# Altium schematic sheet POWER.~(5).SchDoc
size 431 x 279 mm; Date: Not shown in title block; ApprovedBy: Not shown in title block; CheckedBy: Not shown in title block; Author: Not shown in title block; CompanyName: Not shown in title block; DrawnBy: G. Fiolic; Engineer: Not shown in title block; Organization: Not shown in title block; Address1: Not shown in title block; Address2: Not shown in title block; Address3: Not shown in title block; Address4: Not shown in title block; DocumentNumber: 3; Revision: Use project parameter SCH_Rev; SheetNumber: 3; SheetTotal: 6; PageSetup: Record=PageOptions|CenterHorizontal=True|CenterVertical=True|PrintScale=1.00|XCorrection=1.00|YCorrection=1.00|PrintKind=0|BorderSize=5000000|LeftOffset=0|BottomOffset=0|Orientation=2|PaperLength=1000|PaperWidth=1000|Scale=100|PaperSource=15|PrintQuality=600|MediaType=1|DitherType=10|PaperKind=Letter|PrintScaleMode=1
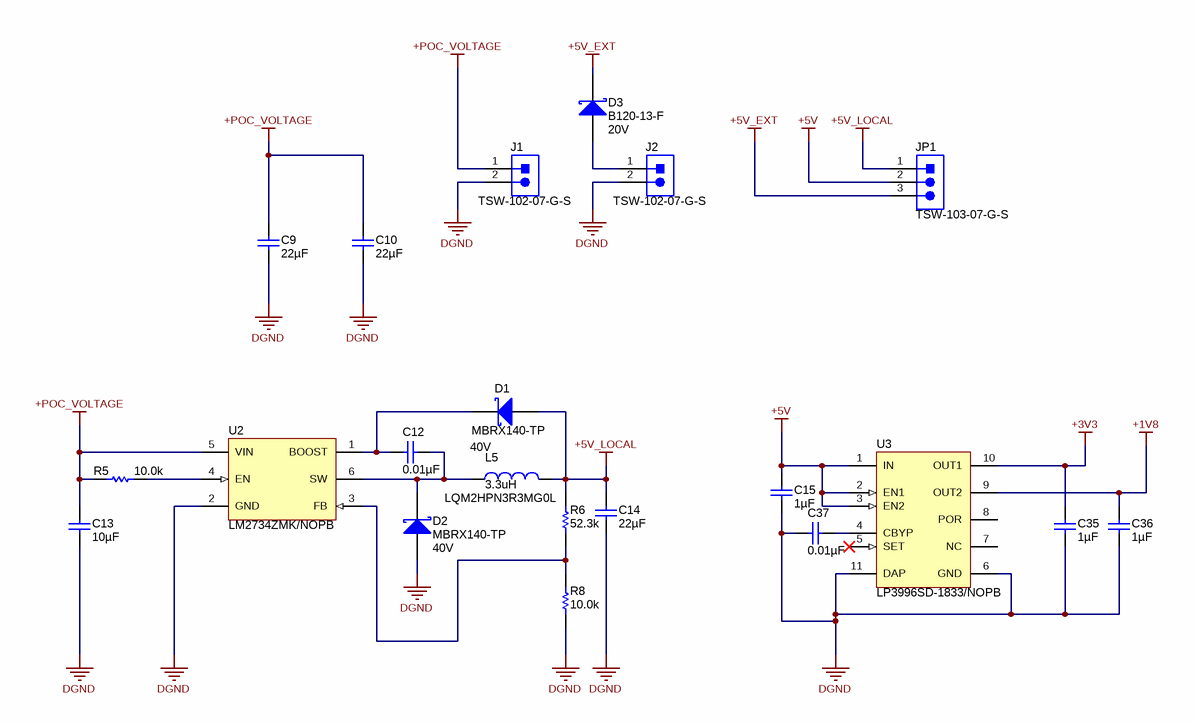
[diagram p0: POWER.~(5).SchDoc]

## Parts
C9  ValueDisplayed: 22µF  [0805]  (hidden comment: C2012X5R1C226K125AC)
C10  ValueDisplayed: 22µF  [0805]  (hidden comment: C2012X5R1C226K125AC)
C12  ValueDisplayed: 0.01µF  [0402L]  (hidden comment: GRM155R71H103KA88D)
C13  ValueDisplayed: 10µF  [1206L]  (hidden comment: GRM31CR71E106KA12L)
C14  ValueDisplayed: 22µF  [0805]  (hidden comment: C2012X5R1C226K125AC)
C15  ValueDisplayed: 1µF  [0402]  (hidden comment: GRM155R61A105KE15D)
C35  ValueDisplayed: 1µF  [0402]  (hidden comment: GRM155R61A105KE15D)
C36  ValueDisplayed: 1µF  [0402]  (hidden comment: GRM155R61A105KE15D)
C37  ValueDisplayed: 0.01µF  [0402L]  (hidden comment: GRM155R71H103KA88D)
D1  MBRX140-TP  value 40V  [SOD-123]
D2  MBRX140-TP  value 40V  [SOD-123]
D3  B120-13-F  value 20V  [SMA]
J1  TSW-102-07-G-S  [TSW-102-07-G-S]
J2  TSW-102-07-G-S  [TSW-102-07-G-S]
JP1  TSW-103-07-G-S  [TSW-103-07-G-S]
L5  LQM2HPN3R3MG0L  value 3.3uH  [IND_1008]
R5  value 10.0k  [0402L]  (hidden comment: CRCW040210K0FKED)
R6  value 52.3k  [0402]  (hidden comment: CRCW040252K3FKED)
R8  value 10.0k  [0402L]  (hidden comment: CRCW040210K0FKED)
U2  LM2734ZMK/NOPB  [MK06A_N]
U3  LP3996SD-1833/NOPB  [SDA10A]

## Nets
+1V8: C36.1 U3.9(OUT2)
+3V3: C35.1 U3.10(OUT1)
+5V: C15.1 JP1.2 U3.1(IN) U3.2(EN1) U3.3(EN2)
+5V_EXT: D3.1(K) JP1.3
+5V_LOCAL: C14.1 D1.2(A) JP1.1 L5.2 R6.2
+POC_VOLTAGE: C9.1 C10.1 C13.1 J1.1 R5.1 U2.5(VIN)
DGND: C9.2 C10.2 C13.2 C14.2 C15.2 C35.2 C36.2 C37.1 D2.2(A) J1.2 J2.2 R8.2 U2.2(GND) U3.6(GND) U3.11(DAP)
NetC12_1: C12.1 D1.1(K) U2.1(BOOST)
NetC12_2: C12.2 D2.1(K) L5.1 U2.6(SW)
NetC37_2: C37.2 U3.4(CBYP)
NetD3_2: D3.2(A) J2.1
NetR5_2: R5.2 U2.4(EN)
NetR6_1: R6.1 R8.1 U2.3(FB)

Not connected (* = marked no-connect by the designer): U3 5(SET)* 7(NC) 8(POR)

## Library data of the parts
C9 C10 C14 = C2012X5R1C226K125AC: CAP, CERM, 22uF, 16V, +/-10%, X5R, 0805; Manufacturer: TDK; Polarized: N; CompType: Capacitor; U/M: EA; Cap_F: 0.000022; Tolerance_%: 10; Value1: Unknown; VDC_V: 16; TaMin_C: -55; TaMax_C: 85
C12 C37 = GRM155R71H103KA88D: CAP, CERM, 0.01uF, 50V, +/-10%, X7R, 0402; Manufacturer: MuRata; Polarized: N; CompType: Capacitor; U/M: EA; Cap_F: 0.00000001; Tolerance_%: 10; Value1: Unknown; VDC_V: 50; TaMin_C: -55; TaMax_C: 125; Cap_Case: 0402
C13 = GRM31CR71E106KA12L: CAP, CERM, 10uF, 25V, +/-10%, X7R, 1206; Manufacturer: MuRata; Polarized: N; CompType: Capacitor; U/M: EA; Cap_F: 0.00001; Tolerance_%: 10; Value1: Unknown; VDC_V: 25; TaMin_C: -55; TaMax_C: 125; Cap_Case: 2220
C15 C35 C36 = GRM155R61A105KE15D: CAP, CERM, 1uF, 10V, +/-10%, X5R, 0402; Manufacturer: MuRata; Polarized: N; CompType: Capacitor; U/M: EA; Cap_F: 0.000001; Tolerance_%: 10; Value1: Unknown; TaMin_C: -55; TaMax_C: 85
D1 D2 = Diode_Schottky: Diode, Schottky, 40V, 1A, SOD-123; Manufacturer: Micro Commercial Co; U/M: EA
D3 = B120-13-F: Diode, Schottky, 20V, 1A, SMA; Manufacturer: Diodes Inc.; U/M: EA; Vf_V: 0.5; Value2: 0.5V; Io_A: 1; Vr_V: 20; TJmax_C: 150
J1 J2 = TSW-102-07-G-S: Header, TH, 100mil, 2x1, Gold plated, 230 mil above insulator; Manufacturer: Samtec; SymbolCreator: a0412235; U/M: EA
JP1 = TSW-103-07-G-S: Header, TH, 100mil, 3x1, Gold plated, 230 mil above insulator; Manufacturer: Samtec; SymbolCreator: a0799628; U/M: EA
L5 = Inductor: Inductor, Shielded 3.3uH, 1200mA, 100 mohm, Surface Mount; Manufacturer: Murata Electronics North America; U/M: EA
R5 R8 = CRCW040210K0FKED: RES, 10.0k ohm, 1%, 0.063W, 0402; Manufacturer: Vishay-Dale; CompType: Resistor; Res_ohm: 10000; Value_Code: 10k0; Tolerance_%: 1; Power_W: 0.063; VDC_V: 50; TempCo: 100 ppm/C; EIA_Code: E96; U/M: EA
R6 = CRCW040252K3FKED: RES, 52.3k ohm, 1%, 0.063W, 0402; Manufacturer: Vishay-Dale; CompType: Resistor; Res_ohm: 52300; Value_Code: 52k3; Tolerance_%: 1; Power_W: 0.063; VDC_V: 50; TempCo: 100 ppm/C; EIA_Code: E96; U/M: EA
U2 = LM2734ZMK/NOPB: 1A Load Step-Down DC-DC Regulator, 6-pin Tiny SOT23, Pb-Free; Manufacturer: National Semiconductor; PackageTopMarking: SFTB*XTT; PowerWise: N; CompType: Switcher
U3 = LP3996SD-1833/NOPB: Dual Linear Regulator with 300mA and 150mA Outputs and Power-On-Reset, 10-pin LLP, Pb-Free; Manufacturer: National Semiconductor; PackageTopMarking: ZXYTT*L228B; PowerWise: N; CompType: LDO IC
